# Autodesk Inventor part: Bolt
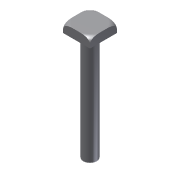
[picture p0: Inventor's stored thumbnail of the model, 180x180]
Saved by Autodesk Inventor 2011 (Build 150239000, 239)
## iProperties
Created: 2009-04
Part Number: Bolt
Document SubType Name: Modeling
Designer: Sham
Density: 1 g/cm^3
Author: Sham
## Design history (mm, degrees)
sketch "Sketch1"
  geometry: L1 (-12, 12)-(12, 12); L2 (12, 12)-(12, -12); L3 (12, -12)-(-12, -12); L4 (-12, -12)-(-12, 12); 1 further point
  constraints: 8 end point, 2 parallel, 2 perpendicular, 1 horizontal, 1 other
  dimensions: "d0" = 24 distance of L1.start L1.end; "d1" = 12 distance from line of L2 point (0, 0); "d2" = 12 distance from line of L1 point (0, 0)
extrude "Extrusion1" new body sketch "Sketch1" distance "d3" = 8; taper "d4" = 0 deg
sketch "Sketch2"
  geometry: C1 r 6 at (0, 0)
  constraints: 1 centre point
  dimensions: "d5" = 12 diameter of C1
extrude "Extrusion2" join sketch "Sketch2" distance "d6" = 96; taper "d7" = 0 deg
workpoint "Work Point1"
workplane "Work Plane1"
sketch "Sketch3"
  geometry: L1 (33.941, 5)-(33.941, 6); L2 (28.941, 0)-(28.405, 0); L3 (16.971, 125.007)-(16.971, -22.043) reference; A1 r 5 centre (28.941, 5) between (28.941, 0) and (33.941, 5); 1 further point
  constraints: 4 end point, 2 point on circle, 2 point on line, 2 tangent, 1 centre point, 1 perpendicular
  dimensions: "d10" = 5 radius of A1
revolve "Revolution1" sketch "Sketch3" stored, may be unused: angle "d12" = 90 deg
body "Solid1"
other parameters: "d11" = 90 deg
